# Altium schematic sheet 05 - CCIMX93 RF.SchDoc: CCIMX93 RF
size A3; PageSetup: Record=PageOptions¦CenterHorizontal=True¦CenterVertical=True¦PrintScale=0.70¦XCorrection=1.00¦YCorrection=1.00¦PrintKind=0¦BorderSize=5000000¦LeftOffset=0¦BottomOffset=0¦Orientation=2¦PaperLength=4200¦PaperWidth=2970¦Scale=100¦PaperSource=7¦PrintQuality=600¦MediaType=1¦DitherType=10¦PaperKind=A4¦PrintScaleMode=1; Author: Juan Anzola; SheetNumber: 5; SheetTotal: 20
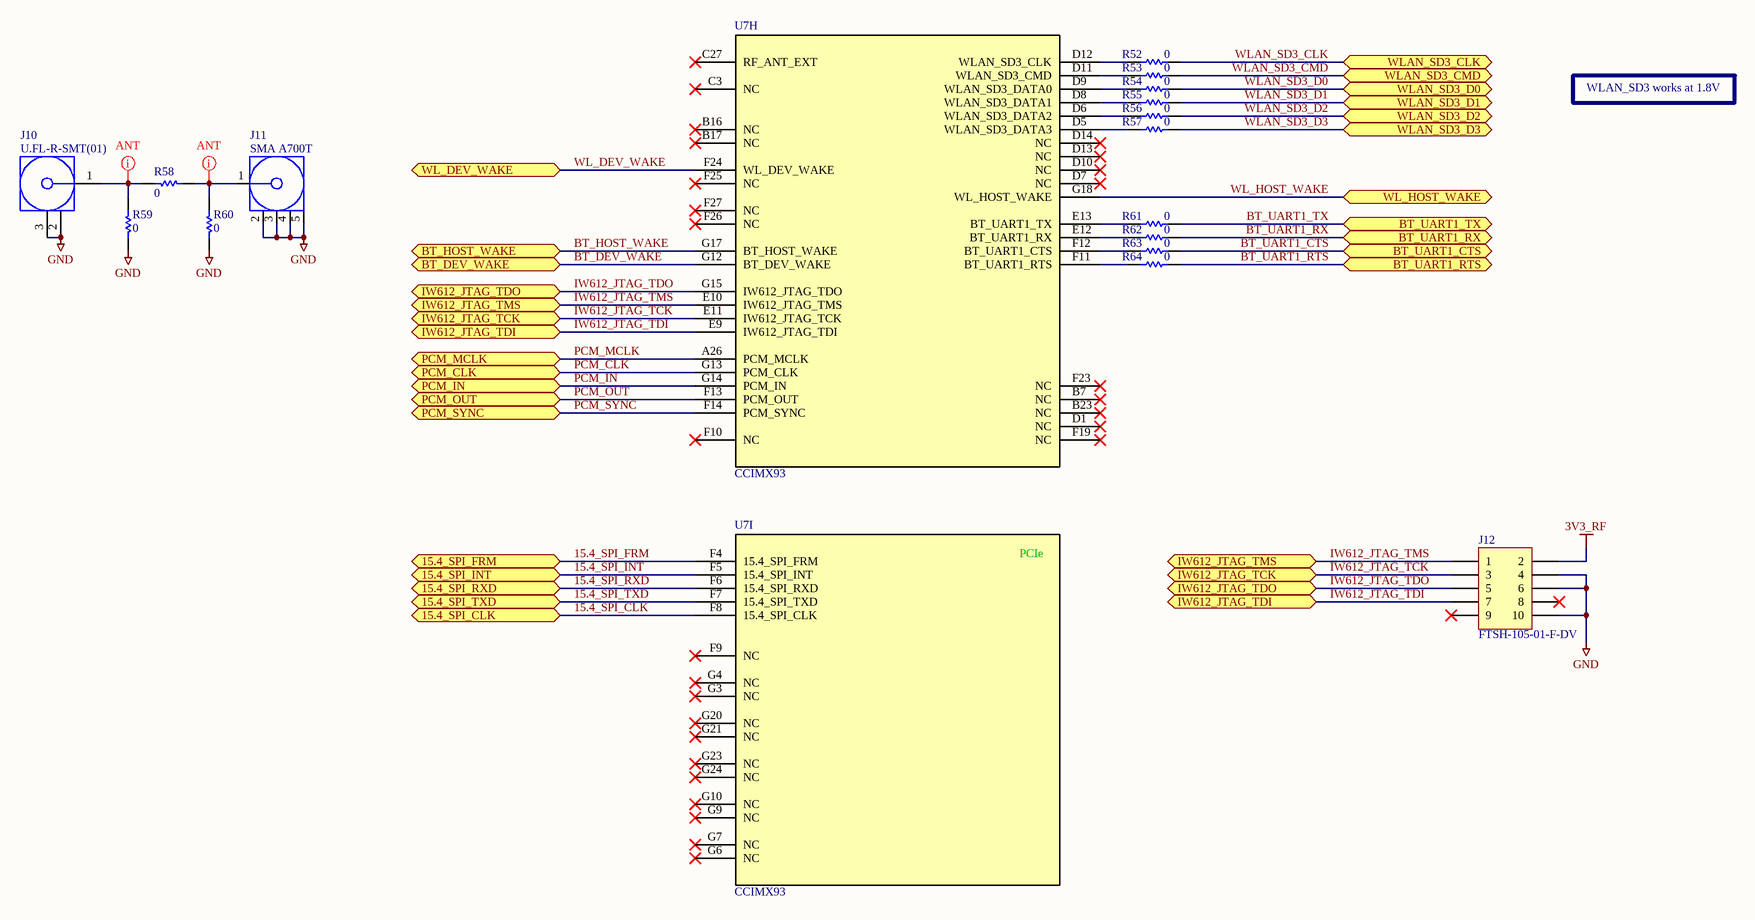
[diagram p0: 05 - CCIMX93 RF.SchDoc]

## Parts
J10  U.FL-R-SMT(01)  [HIROSE_U.FL-R-SMT(01)]
J11  SMA A700T  [BOBBINTRON_SMA A700T]
J12  FTSH-105-01-F-DV  [SAMTEC_FTSH-105-01-F-DV]
R52  0  [RESC1005X40N]
R53  0  [RESC1005X40N]
R54  0  [RESC1005X40N]
R55  0  [RESC1005X40N]
R56  0  [RESC1005X40N]
R57  0  [RESC1005X40N]
R58  0  [RESC1005X40N]
R59  0  [RESC1005X40N]
R60  0  [RESC1005X40N]
R61  0  [RESC1005X40N]
R62  0  [RESC1005X40N]
R63  0  [RESC1005X40N]
R64  0  [RESC1005X40N]
U7  CCIMX93  [CC93_DVK]  (parts H,I of 10)

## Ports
15.4_SPI_CLK (bidir), 15.4_SPI_FRM (bidir), 15.4_SPI_INT (bidir), 15.4_SPI_RXD (bidir), 15.4_SPI_TXD (bidir), BT_DEV_WAKE (bidir), BT_HOST_WAKE (bidir), BT_UART1_CTS (bidir), BT_UART1_RTS (bidir), BT_UART1_RX (bidir), BT_UART1_TX (bidir), IW612_JTAG_TCK (bidir), IW612_JTAG_TDI (bidir), IW612_JTAG_TDO (bidir), IW612_JTAG_TMS (bidir), PCM_CLK (bidir), PCM_IN (bidir), PCM_MCLK (bidir), PCM_OUT (bidir), PCM_SYNC (bidir), WL_DEV_WAKE (bidir), WL_HOST_WAKE (bidir), WLAN_SD3_CLK (bidir), WLAN_SD3_CMD (bidir), WLAN_SD3_D0 (bidir), WLAN_SD3_D1 (bidir), WLAN_SD3_D2 (bidir), WLAN_SD3_D3 (bidir)

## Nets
3V3_RF: J12.2
GND: J10.2(GND) J10.3(GND) J11.2(GND) J11.3(GND) J11.4(GND) J11.5(GND) J12.4 J12.6 J12.10 R59.1 R60.1
15.4_SPI_CLK: U7.F8(15.4_SPI_CLK) ; port 15.4_SPI_CLK
15.4_SPI_FRM: U7.F4(15.4_SPI_FRM) ; port 15.4_SPI_FRM
15.4_SPI_INT: U7.F5(15.4_SPI_INT) ; port 15.4_SPI_INT
15.4_SPI_RXD: U7.F6(15.4_SPI_RXD) ; port 15.4_SPI_RXD
15.4_SPI_TXD: U7.F7(15.4_SPI_TXD) ; port 15.4_SPI_TXD
BT_DEV_WAKE: U7.G12(BT_DEV_WAKE) ; port BT_DEV_WAKE
BT_HOST_WAKE: U7.G17(BT_HOST_WAKE) ; port BT_HOST_WAKE
BT_UART1_CTS: R63.2 ; port BT_UART1_CTS
BT_UART1_RTS: R64.2 ; port BT_UART1_RTS
BT_UART1_RX: R62.2 ; port BT_UART1_RX
BT_UART1_TX: R61.2 ; port BT_UART1_TX
IW612_JTAG_TCK: J12.3 U7.E11(IW612_JTAG_TCK) ; port IW612_JTAG_TCK
IW612_JTAG_TDI: J12.7 U7.E9(IW612_JTAG_TDI) ; port IW612_JTAG_TDI
IW612_JTAG_TDO: J12.5 U7.G15(IW612_JTAG_TDO) ; port IW612_JTAG_TDO
IW612_JTAG_TMS: J12.1 U7.E10(IW612_JTAG_TMS) ; port IW612_JTAG_TMS
PCM_CLK: U7.G13(PCM_CLK) ; port PCM_CLK
PCM_IN: U7.G14(PCM_IN) ; port PCM_IN
PCM_MCLK: U7.A26(PCM_MCLK) ; port PCM_MCLK
PCM_OUT: U7.F13(PCM_OUT) ; port PCM_OUT
PCM_SYNC: U7.F14(PCM_SYNC) ; port PCM_SYNC
WL_DEV_WAKE: U7.F24(WL_DEV_WAKE) ; port WL_DEV_WAKE
WL_HOST_WAKE: U7.G18(WL_HOST_WAKE) ; port WL_HOST_WAKE
WLAN_SD3_CLK: R52.2 ; port WLAN_SD3_CLK
WLAN_SD3_CMD: R53.2 ; port WLAN_SD3_CMD
WLAN_SD3_D0: R54.2 ; port WLAN_SD3_D0
WLAN_SD3_D1: R55.2 ; port WLAN_SD3_D1
WLAN_SD3_D2: R56.2 ; port WLAN_SD3_D2
WLAN_SD3_D3: R57.2 ; port WLAN_SD3_D3
NetJ10_1: J10.1(Signal) R58.2 R59.2
NetJ11_1: J11.1(Signal) R58.1 R60.2
NetR52_1: R52.1 U7.D12(WLAN_SD3_CLK)
NetR53_1: R53.1 U7.D11(WLAN_SD3_CMD)
NetR54_1: R54.1 U7.D9(WLAN_SD3_DATA0)
NetR55_1: R55.1 U7.D8(WLAN_SD3_DATA1)
NetR56_1: R56.1 U7.D6(WLAN_SD3_DATA2)
NetR57_1: R57.1 U7.D5(WLAN_SD3_DATA3)
NetR61_1: R61.1 U7.E13(BT_UART1_TX)
NetR62_1: R62.1 U7.E12(BT_UART1_RX)
NetR63_1: R63.1 U7.F12(BT_UART1_CTS)
NetR64_1: R64.1 U7.F11(BT_UART1_RTS)

Not connected (* = marked no-connect by the designer): J12 8* 9*; U7 B7(NC)* B16(NC)* B17(NC)* B23(NC)* C3(NC)* C27(RF_ANT_EXT)* D1(NC)* D7(NC)* D10(NC)* D13(NC)* D14(NC)* F9(NC)* F10(NC)* F19(NC)* F23(NC)* F25(NC)* F26(NC)* F27(NC)* G3(NC)* G4(NC)* G6(NC)* G7(NC)* G9(NC)* G10(NC)* G20(NC)* G21(NC)* G23(NC)* G24(NC)*

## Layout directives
net class ANT: NetJ10_1, NetJ11_1

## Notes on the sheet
- WLAN_SD3 works at 1.8V

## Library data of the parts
J10 = 1000027: RF Connectors U.FL RECEPTACLE SMT GLD M CONTACT; Manufacturer: Hirose; Digi_PN: 18000684; Component_Life_Cycle_State: Proven; Area: 14,4
J11 = 1002720: CONN SMA JACK R/A 50 OHM L15.1MM PCB TH; Part_Type: Connector; Manufacturer: Bobbintron Electrical Corp; Digi_PN: MA02979; Component_Life_Cycle_State: Reviewed; Area: 121,68
J12 = 1000034: CONN HEADER 10POS DUAL .05" SMD; Part_Type: Connector; Manufacturer: Samtec; Note: 18000715 = Digi No. for GE WDNU; Digi_PN: 18000539; Component_Life_Cycle_State: Proven; Area: 43,55
R52-R57 R61-R64 = 1000076: RES 0.0 OHM 1/10W 0402 SMD; Part_Type: Resistor; Manufacturer: Panasonic - ECG; Manufacturer_Part_Number: ERJ-2GE0R00X; Component_Life_Cycle_State: Proven; Area: 0.95; Project: Adjustable Foundation; Power_WV_SRF: 10; Digi_PN: 13050387
R58-R60 = 1000076: RES 0.0 OHM 1/10W 0402 SMD; Part_Type: Resistor; Manufacturer: Panasonic - ECG; Manufacturer_Part_Number: ERJ-2GE0R00X; Digi_PN: 13050387; Component_Life_Cycle_State: Proven; Area: 0,95; Project: Adjustable Foundation; Power_WV_SRF: 10
U7 = 1002856: ConnectCore for i.MX93 module; Manufacturer: DIGI; Digi_PN: 55002169-01; Component_Life_Cycle_State: Pending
